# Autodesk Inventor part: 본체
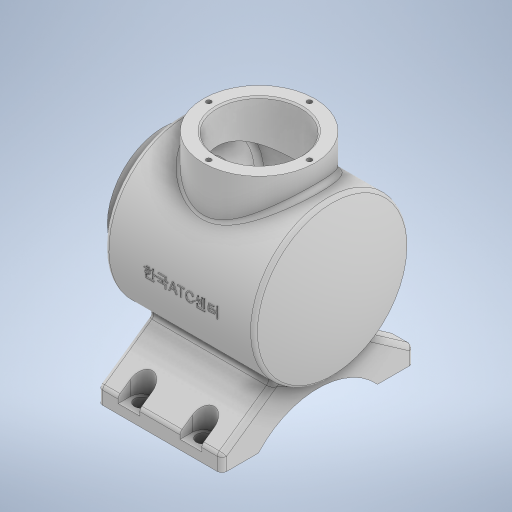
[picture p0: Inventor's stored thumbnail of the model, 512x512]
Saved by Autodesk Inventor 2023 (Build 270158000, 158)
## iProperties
Created: 2023-12
Part Number: 본체
Material: 일반
Document SubType Name: Modeling
Designer: asung
Density: 1 g/cm^3
Appearance: 기본값
Author: asung
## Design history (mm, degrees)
sketch "스케치1"
  geometry: L1 (0, 0)-(120, 0); L2 (0, 0)-(0, 36); L3 (0, 36)-(12, 36); L4 (12, 36)-(12, 50); L5 (12, 50)-(108.336, 50); L6 (0, 0)-(0, -36); L7 (0, -36)-(12, -36); L8 (12, -50)-(108.336, -50); L9 (12, -36)-(12, -50); L10 (0, 0)-(0, 27); L11 (0, 27)-(19, 27); L12 (19, 27)-(19, 43); L13 (19, 43)-(103.887, 43); A1 r 113 centre (7, 0) between (108.336, -50) and (108.336, 50); A2 r 106 centre (7, 0) between (113, 0) and (103.887, 43); 1 further point
  constraints: 26 end point, 6 perpendicular, 6 point on circle, 3 symmetric about line, 2 centre point, 2 point on line, 1 horizontal, 1 vertical
  dimensions: "d0" = 120 distance of L1.end L1.start; "d1" = 36 distance of L1.start L2.end; "d3" = 100 diameter of L5 L1; "d5" = 113 radius of A1; "d6" = 120 horizontal distance of point (120, 0) L2.end; "d7" = 108 horizontal distance of L1.end L4.end; "d8" = 27 distance of L1.start L10.end; "d9" = 19 distance of L10.end L11.end; "d10" = 86 diameter of L13 L1; "d11" = 7 radial gap between concentric circles of A1 A2; "d12" = 7 radial gap between concentric circles of A1 A2 (derived)
revolve "회전1" sketch "스케치1" stored, may be unused: angle "d13" = 360 deg
fillet "모깎기1" dims "d14" = 3
sketch "스케치3" dims "d15" = 65
  geometry: C1 r 27 at (0, 0) reference; C2 r 36 at (0, 0) reference; 3 further points
  constraints: 1 coincident, 1 vertical alignment, 2 other
hole "구멍1" sketch "스케치3" at (0, 32.5) diameter "d16" = 3.242; stored, may be unused: countersink angle "d20" = 90 deg, drill point angle "d22" = 118 deg; dims "d17" = 8, "d18" = 4, "d19" = 2, "d21" = 10
node "작업 평면1"
sketch "스케치4"
  geometry: L1 (0, 36)-(0, -36) reference; C1 r 36 at (-62, 0); 2 further points
  constraints: 1 centre point, 1 horizontal alignment, 1 midpoint
  dimensions: "d27" = 72 diameter of C1; "d28" = 62 distance from line of C1.centre L1
extrude "돌출1" join sketch "스케치4" stored distance "d29" = 10; taper "d30" = 0 deg
sketch "스케치5"
  geometry: C1 r 36 at (0, 0) reference; 2 further points
  constraints: 1 coincident
hole "구멍2" sketch "스케치5" at (0, 0) diameter "d31" = 54; stored, may be unused: countersink angle "d35" = 90 deg, drill point angle "d37" = 0 deg; dims "d32" = 8, "d33" = 4, "d34" = 2, "d36" = 50
sketch "스케치6" dims "d38" = 65
  geometry: C1 r 27 at (0, 0) reference; C2 r 36 at (0, 0) reference; 3 further points
  constraints: 1 coincident, 1 vertical alignment, 2 other
hole "구멍3" sketch "스케치6" at (0, 32.5) diameter "d39" = 3.242; stored, may be unused: countersink angle "d43" = 90 deg, drill point angle "d45" = 118 deg; dims "d40" = 8, "d41" = 4, "d42" = 2, "d44" = 10
chamfer "모따기1" distance "d49" = 1; stored, may be unused: second distance "d50" = 2, angle "d51" = 45 deg
fillet "모깎기2" dims "d52" = 3
node "작업 평면2"
sketch "스케치7"
  geometry: L1 (0, 0)-(0, -77); L2 (-38.5, -77)-(38.5, -77); L3 (38.5, -77)-(62, -77); L4 (62, -77)-(62, -67); L5 (62, -67)-(26.694, -42.278); L6 (-38.5, -77)-(-62, -77); L7 (-62, -77)-(-62, -67); L8 (-62, -67)-(-26.694, -42.278); C1 r 42.236 at (0, 0) reference; A1 r 50 centre (0, 0) between (26.694, -42.278) and (-26.694, -42.278) reference; A2 r 52.096 centre (0, -112.096) between (38.5, -77) and (-38.5, -77); 2 further points
  constraints: 16 end point, 5 point on circle, 3 horizontal, 2 perpendicular, 1 centre point, 1 midpoint, 1 vertical
  dimensions: "d54" = 77 distance of L1.end L1.start; "d55" = 77 distance of L2.start L2.end; "d57" = 17 distance of L1.end point (0, -60); "d58" = 23.5 distance of L2.end L3.end; "d59" = 10 distance of L3.end L4.end; "d60" = 55 deg angle of L4 L5; "d61" = 23.5 distance of L2.start L6.end; "d62" = 10 distance of L6.end L7.end; "d64" = 55 deg angle of L8 L7
extrude "돌출2" join sketch "스케치7" distance "d65" = 80; taper "d66" = 0 deg
sketch "스케치8"
  geometry: L1 (0, -100.5)-(0, -77) reference; L2 (0, -100.5)-(80, -100.5) reference; L3 (80, -77)-(80, -100.5) reference; L4 (0, -77)-(80, -77) reference; L5 (0, 0)-(0, 23.5) reference; L6 (0, 0)-(80, 0) reference; L7 (80, 23.5)-(80, 0) reference; L8 (0, 23.5)-(80, 23.5) reference; L9 (0, -77)-(0, 0) reference; L10 (0, -77)-(80, -77) reference; L11 (80, 0)-(80, -77) reference; L12 (0, 0)-(80, 0) reference; L13 (40, -100.5)-(40, -38.5); L14 (60, -92.5)-(20, -92.5); L15 (20, -92.5)-(20, 15.5); L16 (20, 15.5)-(60, 15.5); L17 (60, 15.5)-(60, -92.5); L18 (60, -92.5)-(20, 15.5); L19 (20, -92.5)-(60, 15.5); 1 further point
  constraints: 14 end point, 3 midpoint, 2 parallel, 1 horizontal, 1 perpendicular, 1 vertical
  dimensions: "d67" = 62 distance of L13.start L13.end; "d68" = 40 distance of L15.end L16.end; "d69" = 108 distance of L14.end L15.end
hole "구멍4" sketch "스케치8" at (20, -92.5), (60, -92.5), (60, 15.5), (20, 15.5) diameter "d70" = 9; stored, may be unused: countersink angle "d74" = 90 deg, drill point angle "d76" = 0 deg; dims "d71" = 8, "d72" = 4, "d73" = 2, "d75" = 6
node "작업 평면3"
sketch "스케치9"
  geometry: L1 (0, 29.983)-(80, 29.983) reference; L2 (80, 29.983)-(80, 0) reference; L3 (80, 0)-(0, 0) reference; L4 (0, 0)-(0, 29.983) reference; L5 (0, 124)-(80, 124) reference; L6 (80, 124)-(80, 94.017) reference; L7 (80, 94.017)-(0, 94.017) reference; L8 (0, 94.017)-(0, 124) reference; C1 r 4.5 at (60, 116) reference; C2 r 4.5 at (20, 8) reference; C3 r 4.5 at (60, 8) reference; C4 r 4.5 at (20, 116) reference; 1 further point
  node "절단 모서리 투영2"
sketch "스케치10"
  geometry: L1 (0, 124)-(80, 124) reference; L2 (0, 124)-(0, 88.694) reference; L3 (13, 116)-(13, 124); L4 (27, 116)-(27, 124); L5 (20, 116)-(60, 116); L6 (53, 116)-(53, 124); L7 (67, 116)-(67, 124); L8 (0, 23.5)-(0, 100.5) reference; L9 (0, 88.694)-(0, 35.306) reference; L10 (0, 62)-(-34.043, 62); L11 (13, 8)-(13, 0); L12 (27, 8)-(27, 0); L13 (53, 8)-(53, 0); L14 (67, 8)-(67, 0); L15 (13, 0)-(13, -7.523); L16 (13, -7.523)-(27, -7.523); L17 (27, -7.523)-(27, 0); L18 (53, 0)-(53, -11.643); L19 (53, -11.643)-(67, -11.643); L20 (67, -11.643)-(67, 0); A1 r 7 centre (20, 116) between (13, 116) and (27, 116); A2 r 7 centre (60, 116) between (53, 116) and (67, 116); A3 r 7 centre (20, 8) between (27, 8) and (13, 8); A4 r 7 centre (60, 8) between (67, 8) and (53, 8); 3 further points
  constraints: 32 end point, 10 symmetric about line, 8 point on circle, 5 perpendicular, 4 centre point, 4 vertical, 2 horizontal, 2 point on line, 1 midpoint, 2 other
  dimensions: "d85" = 14 diameter of A1; "d86" = 8 distance from line of L5.start L1; "d87" = 20 distance from line of L5.start L2; "d88" = 14 distance between parallel lines of L4 L3; "d89" = 40 distance of L5.start L5.end; "d90" = 14 diameter of A2; "d91" = 14 distance between parallel lines of L7 L6
extrude "돌출3" cut sketch "스케치10" distance "d92" = 30; taper "d93" = 0 deg
fillet "모깎기3" dims "d94" = 3
fillet "모깎기4" dims "d95" = 3
node "작업 평면4"
sketch "스케치11"
  geometry: L1 (-60.168, -36)-(-60.168, 36) reference; 3 further points
  constraints: 1 horizontal alignment, 1 midpoint, 1 other
  dimensions: "d96" = 62 distance from line of point (1.832, 0) L1
feature "엠보싱1" sketch "스케치11" dims "d0" = 120, "d1" = 36, "d3" = 100, "d5" = 113, "d6" = 120, "d7" = 108, "d8" = 27, "d9" = 19, "d10" = 86, "d11" = 7, "d12" = 7 (derived), "d14" = 3, "d97" = 0.5, "d98" = 0
node "솔리드1"
pattern_circular "원형 패턴1" dims angle "d24" = 360 deg
pattern_circular "원형 패턴2" dims angle "d47" = 360 deg
node "투영된 루프1"
node "투영된 루프2"
node "투영된 루프3"
node "투영된 루프4"
node "투영된 루프5"
node "절단 모서리 투영1"
feature "A9D066F2-1C7D-4E18-AEED-F7BC21143FA4" dims "d31" = 54, "d32" = 8, "d33" = 4, "d34" = 2, "d35" = 90 deg, "d36" = 50, "d37" = 0
other parameters: "d26" = 65, "d63" = 55 deg, "d77" = -6
